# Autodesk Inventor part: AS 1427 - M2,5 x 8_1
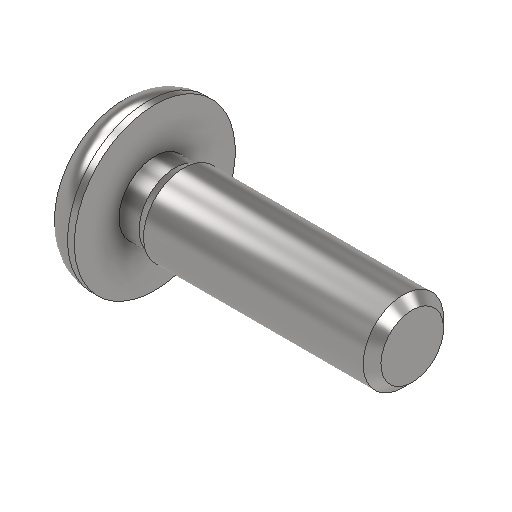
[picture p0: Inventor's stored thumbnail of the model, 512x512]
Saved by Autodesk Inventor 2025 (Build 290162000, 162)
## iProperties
Created: 2021-02
Part Number: AS 1427 - M2,5 x 8_1
Material: Acciaio, Dolce
Description: Phillips Viti metriche ISO
Document SubType Name: Modeling
Designer: Ryzen5700u
Density: 7.85 g/cm^3
Appearance: Default
Author: Ryzen5700u
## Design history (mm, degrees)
feature "Solid1"
node "Solido1"
